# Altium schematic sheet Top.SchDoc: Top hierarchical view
size A4; Date: Not used; ApprovedBy: Not used; CheckedBy: Not used; Author: Not used; CompanyName: STMicroelectronics; DrawnBy: Not used; Engineer: Not used; Organization: Not used; Address1: Not used; Address2: Not used; Address3: Not used; Address4: Not used; DocumentNumber: 2; Revision: A-01-P3; SheetNumber: 2; SheetTotal: 8
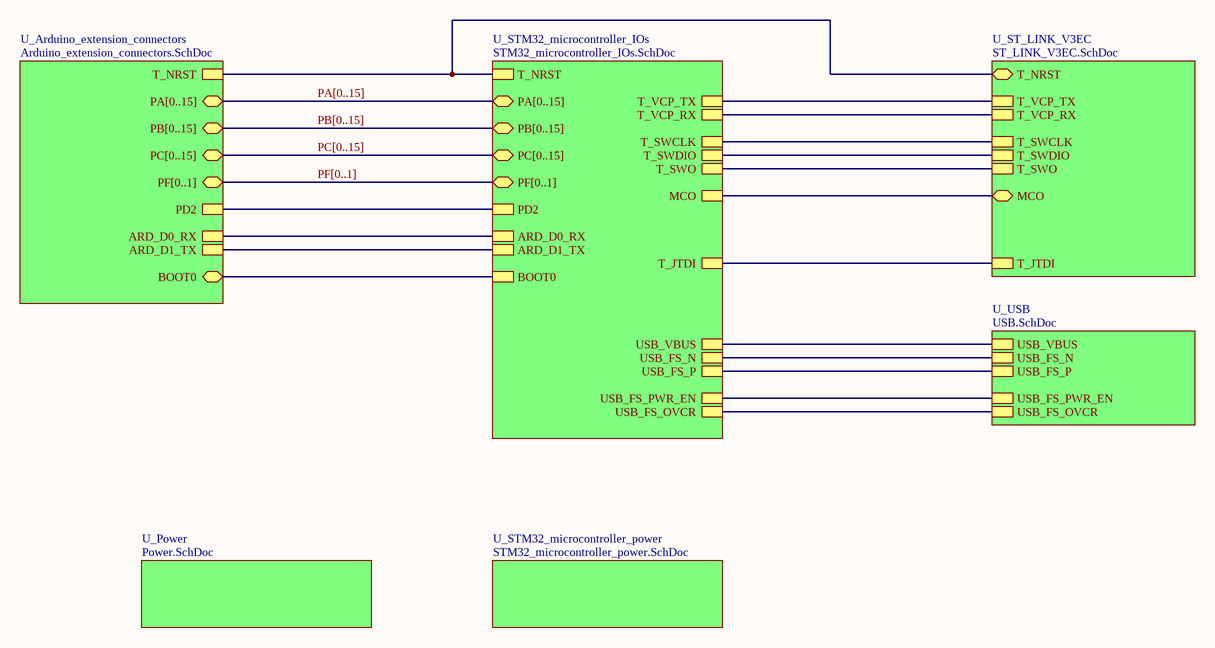
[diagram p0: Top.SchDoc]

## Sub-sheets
U_Arduino_extension_connectors = Arduino_extension_connectors.SchDoc: PA[0..15] (bidir), PB[0..15] (bidir), PC[0..15] (bidir), PD2, PF[0..1] (bidir), ARD_D0_RX, ARD_D1_TX, T_NRST, BOOT0 (bidir)
U_Power = Power.SchDoc: no entries
U_ST_LINK_V3EC = ST_LINK_V3EC.SchDoc: T_NRST (bidir), MCO (bidir), T_VCP_RX, T_VCP_TX, T_JTDI, T_SWCLK, T_SWO, T_SWDIO
U_STM32_microcontroller_IOs = STM32_microcontroller_IOs.SchDoc: PA[0..15] (bidir), PB[0..15] (bidir), PC[0..15] (bidir), PF[0..1] (bidir), ARD_D0_RX, ARD_D1_TX, MCO, PD2, T_NRST, T_VCP_TX, T_VCP_RX, T_SWCLK, T_SWO, T_SWDIO, T_JTDI, USB_FS_N, USB_FS_P, USB_FS_PWR_EN, BOOT0, USB_FS_OVCR, USB_VBUS
U_STM32_microcontroller_power = STM32_microcontroller_power.SchDoc: no entries
U_USB = USB.SchDoc: USB_FS_N, USB_FS_P, USB_FS_PWR_EN, USB_FS_OVCR, USB_VBUS

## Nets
(unnamed): sheet U_Arduino_extension_connectors/PD2, sheet U_STM32_microcontroller_IOs/PD2
(unnamed): sheet U_Arduino_extension_connectors/ARD_D0_RX, sheet U_STM32_microcontroller_IOs/ARD_D0_RX  [a separate net that carries the same name]
(unnamed): sheet U_Arduino_extension_connectors/ARD_D1_TX, sheet U_STM32_microcontroller_IOs/ARD_D1_TX  [a separate net that carries the same name]
(unnamed): sheet U_Arduino_extension_connectors/T_NRST, sheet U_STM32_microcontroller_IOs/T_NRST, sheet U_ST_LINK_V3EC/T_NRST  [a separate net that carries the same name]
(unnamed): sheet U_Arduino_extension_connectors/BOOT0, sheet U_STM32_microcontroller_IOs/BOOT0  [a separate net that carries the same name]
(unnamed): sheet U_STM32_microcontroller_IOs/MCO, sheet U_ST_LINK_V3EC/MCO  [a separate net that carries the same name]
(unnamed): sheet U_STM32_microcontroller_IOs/T_VCP_TX, sheet U_ST_LINK_V3EC/T_VCP_TX  [a separate net that carries the same name]
(unnamed): sheet U_STM32_microcontroller_IOs/T_VCP_RX, sheet U_ST_LINK_V3EC/T_VCP_RX  [a separate net that carries the same name]
(unnamed): sheet U_STM32_microcontroller_IOs/T_SWCLK, sheet U_ST_LINK_V3EC/T_SWCLK  [a separate net that carries the same name]
(unnamed): sheet U_STM32_microcontroller_IOs/T_SWO, sheet U_ST_LINK_V3EC/T_SWO  [a separate net that carries the same name]
(unnamed): sheet U_STM32_microcontroller_IOs/T_SWDIO, sheet U_ST_LINK_V3EC/T_SWDIO  [a separate net that carries the same name]
(unnamed): sheet U_STM32_microcontroller_IOs/T_JTDI, sheet U_ST_LINK_V3EC/T_JTDI  [a separate net that carries the same name]
(unnamed): sheet U_STM32_microcontroller_IOs/USB_FS_N, sheet U_USB/USB_FS_N  [a separate net that carries the same name]
(unnamed): sheet U_STM32_microcontroller_IOs/USB_FS_P, sheet U_USB/USB_FS_P  [a separate net that carries the same name]
(unnamed): sheet U_STM32_microcontroller_IOs/USB_FS_PWR_EN, sheet U_USB/USB_FS_PWR_EN  [a separate net that carries the same name]
(unnamed): sheet U_STM32_microcontroller_IOs/USB_FS_OVCR, sheet U_USB/USB_FS_OVCR  [a separate net that carries the same name]
(unnamed): sheet U_STM32_microcontroller_IOs/USB_VBUS, sheet U_USB/USB_VBUS  [a separate net that carries the same name]

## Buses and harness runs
bus PA[0..15] = sheet U_Arduino_extension_connectors/PA[0..15] = sheet U_STM32_microcontroller_IOs/PA[0..15]
bus PB[0..15] = sheet U_Arduino_extension_connectors/PB[0..15] = sheet U_STM32_microcontroller_IOs/PB[0..15]
bus PC[0..15] = sheet U_Arduino_extension_connectors/PC[0..15] = sheet U_STM32_microcontroller_IOs/PC[0..15]
bus PF[0..1] = sheet U_Arduino_extension_connectors/PF[0..1] = sheet U_STM32_microcontroller_IOs/PF[0..1]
